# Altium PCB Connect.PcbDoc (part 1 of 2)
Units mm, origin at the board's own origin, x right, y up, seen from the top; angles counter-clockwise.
Board outline 500 x 50 mm, 2 copper layers (Top Layer, Bottom Layer); 349 components, 200 nets, 1152 pads, 307 vias.
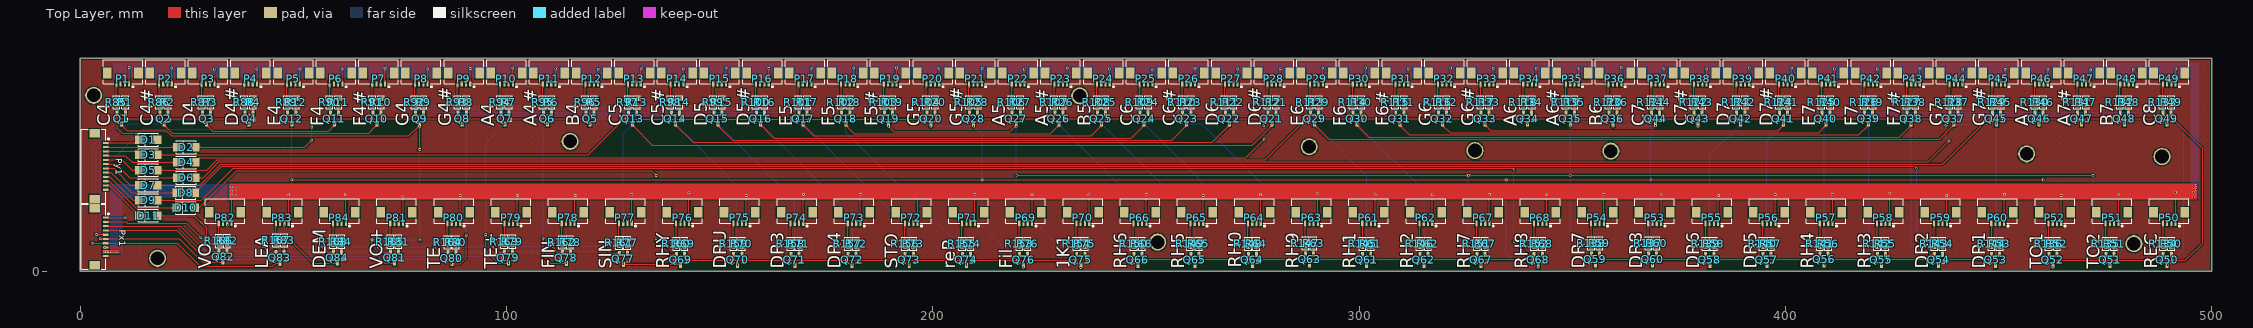
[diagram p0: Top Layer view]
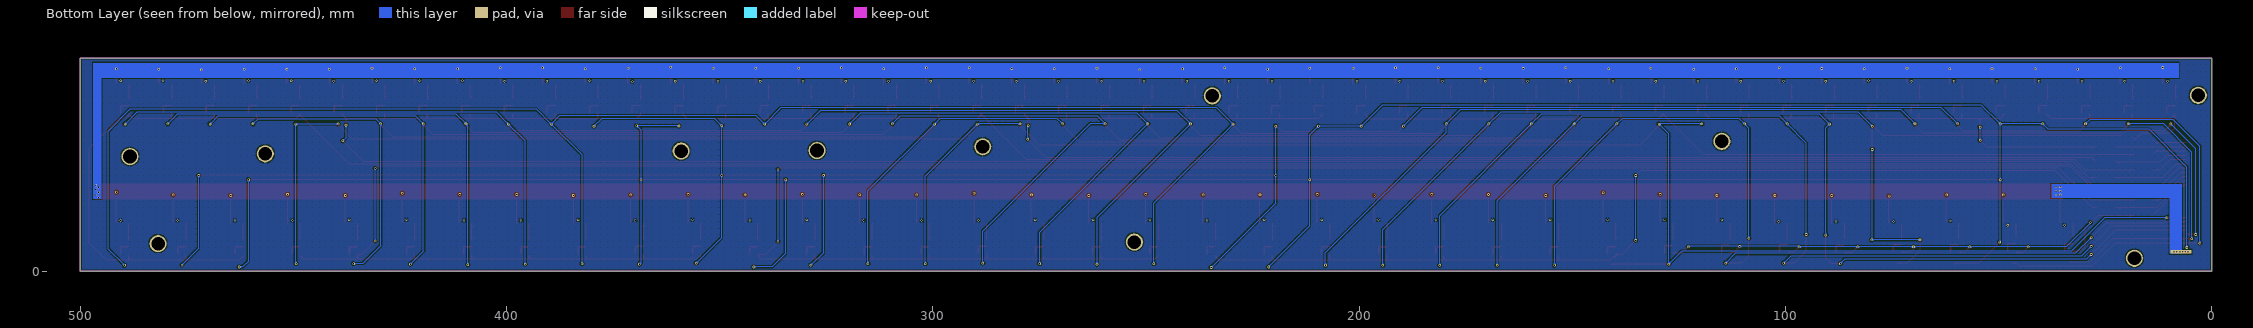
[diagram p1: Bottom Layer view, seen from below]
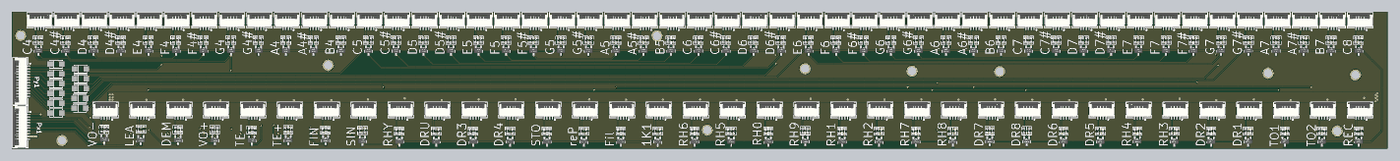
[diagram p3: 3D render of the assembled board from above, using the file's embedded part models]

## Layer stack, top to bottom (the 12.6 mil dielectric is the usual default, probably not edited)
Top Solder: solder mask 0.0102, Solder Resist, Dk 3.5
Top Layer: signal copper 0.0356
Dielectric 1: dielectric 0.32, FR-4, Dk 4.8
Bottom Layer: signal copper 0.0356
Bottom Solder: solder mask 0.0102, Solder Resist, Dk 3.5

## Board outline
0,0 500,0 500,50 0,50

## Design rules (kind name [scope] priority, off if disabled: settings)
Clearance [All] p1: gap=0.254
PolygonConnect [All] p1: connectstyle=Relief reliefconductorwidth=0.254 reliefentries=4 polygonreliefangle="90 Angle" airgapwidth=0.254
RoutingVias [All] p1: holewidth=0.3 width=0.6 viastyle="Through Hole" minholewidth=0.3 minwidth=0.6 maxholewidth=0.711 maxwidth=1.27
SolderMaskExpansion [All] p1: expansion=0.102
Width [All] p1: maxlimit=0.254 minlimit=0.254 preferedwidth=0.254
30 further rules are at their usual default settings.

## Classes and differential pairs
component class Sheet3: D1 D2 D3 D4 D5 D6 D7 D8 D9 D10 D11 Px1 Py1 Q1 Q2 Q3 Q4 Q5 Q6 Q7 Q8 Q9 Q10 Q11 Q12 Q13 Q14 Q15 Q16 Q17 Q18 Q19 Q20 Q21 Q22 Q23 Q24 Q25 Q26 Q27 Q28 Q29 Q30 Q31 Q32 Q33 Q34 Q35 Q36 Q37 Q38 Q39 Q40 Q41 Q42 Q43 Q44 Q45 Q46 Q47 Q48 Q49 Q50 Q51 Q52 Q53 Q54 Q55 Q56 Q57 Q58 Q59 Q60 Q61 Q62 Q63 Q64 Q65 Q66 Q67 Q68 Q69 Q70 Q71 Q72 Q73 Q74 Q75 Q76 Q77 Q79 Q80 Q81 Q82 Q83 Q84 R1 R2 R3 R4 R5 R6 R7 R8 R9 R10 R11 R12 R13 R14 R15 R16 R17 R18 R19 R20 R21 R22 R23 R24 R25 R26 R27 R28 R29 R30 R31 R32 R33 R34 R35 R36 R37 R38 R39 R40 R41 R42 R43 R44 R45 R46 R47 R48 R49 R50 R51 R52 R53 R54 R55 R56 R57 R58 R59 R60 R61 R62 R63 R64 R65 R66 R67 R68 R69 R70 R71 R72 R73 R74 R75 R76 R77 R79 R80 R81 R82 R83 R84
component class CONNECT: P21 P22 P23 P24 P25 P26 P27 P28 P29 P30 P31 P32 P33 P34 P35 P36 P37 P38 P39 P40 P41 P42 P43 P44 P45 P46 P47 P48 P49 P50 P51 P52 P53 P54 P55 P56 P57 P58 P59 P60 P61 P62 P63 P64 P65 P66 P67 P68 P69 P70 P71 P72 P73 P74 P75 P76 P77 P78 P79 P80 P81 P82 P83 P84 R105 R106 R107 R108 R109 R110 R111 R112 R113 R114 R115 R116 R117 R118 R119 R120 R121 R122 R123 R124 R125 R126 R127 R128 R129 R130 R131 R132 R133 R134 R135 R136 R137 R138 R139 R140 R141 R142 R143 R144 R145 R146 R147 R148 R149 R150 R151 R152 R153 R154 R155 R156 R157 R158 R159 R160 R161 R163 R164 R165 R166 R167 R168
component class CONNECT2: P1 P2 P3 P4 P5 P6 P7 P8 P9 P10 P11 P12 P13 P14 P15 P16 P17 P18 P19 P20 R85 R86 R87 R88 R89 R90 R91 R92 R93 R94 R95 R96 R97 R98 R99 R100 R101 R102 R103 R104

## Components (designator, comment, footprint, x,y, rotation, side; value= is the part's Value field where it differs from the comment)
D1 "M7" SMA(DO-214AC)_S1 16.002,30.861 r0 top
D2 "M7" SMA(DO-214AC)_S1 24.892,29.083 r0 top
D3 "M7" SMA(DO-214AC)_S1 16.002,27.305 r0 top
D4 "M7" SMA(DO-214AC)_S1 24.892,25.527 r0 top
D5 "M7" SMA(DO-214AC)_S1 16.002,23.749 r0 top
D6 "M7" SMA(DO-214AC)_S1 24.892,21.971 r0 top
D7 "M7" SMA(DO-214AC)_S1 16.002,20.193 r0 top
D8 "M7" SMA(DO-214AC)_S1 24.765,18.415 r0 top
D9 "M7" SMA(DO-214AC)_S1 16.002,16.637 r0 top
D10 "M7" SMA(DO-214AC)_S1 24.765,14.859 r0 top
D11 "M7" SMA(DO-214AC)_S1 16.002,13.081 r0 top
P1 "Header 4" FPC1.0-2H-WS-4P 10,46.5 r180 top
P2 "Header 4" FPC1.0-2H-WS-4P 20,46.5 r180 top
P3 "Header 4" FPC1.0-2H-WS-4P 30,46.5 r180 top
P4 "Header 4" FPC1.0-2H-WS-4P 40,46.5 r180 top
P5 "Header 4" FPC1.0-2H-WS-4P 50,46.5 r180 top
P6 "Header 4" FPC1.0-2H-WS-4P 60,46.5 r180 top
P7 "Header 4" FPC1.0-2H-WS-4P 70,46.5 r180 top
P8 "Header 4" FPC1.0-2H-WS-4P 80,46.5 r180 top
P9 "Header 4" FPC1.0-2H-WS-4P 90,46.5 r180 top
P10 "Header 4" FPC1.0-2H-WS-4P 100,46.5 r180 top
P11 "Header 4" FPC1.0-2H-WS-4P 110,46.5 r180 top
P12 "Header 4" FPC1.0-2H-WS-4P 120,46.5 r180 top
P13 "Header 4" FPC1.0-2H-WS-4P 130,46.5 r180 top
P14 "Header 4" FPC1.0-2H-WS-4P 140,46.5 r180 top
P15 "Header 4" FPC1.0-2H-WS-4P 150,46.5 r180 top
P16 "Header 4" FPC1.0-2H-WS-4P 160,46.5 r180 top
P17 "Header 4" FPC1.0-2H-WS-4P 170,46.5 r180 top
P18 "Header 4" FPC1.0-2H-WS-4P 180,46.5 r180 top
P19 "Header 4" FPC1.0-2H-WS-4P 190,46.5 r180 top
P20 "Header 4" FPC1.0-2H-WS-4P 200,46.5 r180 top
P21 "Header 4" FPC1.0-2H-WS-4P 210,46.5 r180 top
P22 "Header 4" FPC1.0-2H-WS-4P 220,46.5 r180 top
P23 "Header 4" FPC1.0-2H-WS-4P 230,46.5 r180 top
P24 "Header 4" FPC1.0-2H-WS-4P 240,46.5 r180 top
P25 "Header 4" FPC1.0-2H-WS-4P 250,46.5 r180 top
P26 "Header 4" FPC1.0-2H-WS-4P 260,46.5 r180 top
P27 "Header 4" FPC1.0-2H-WS-4P 270,46.5 r180 top
P28 "Header 4" FPC1.0-2H-WS-4P 280,46.5 r180 top
P29 "Header 4" FPC1.0-2H-WS-4P 290,46.5 r180 top
P30 "Header 4" FPC1.0-2H-WS-4P 300,46.5 r180 top
P31 "Header 4" FPC1.0-2H-WS-4P 310,46.5 r180 top
P32 "Header 4" FPC1.0-2H-WS-4P 320,46.5 r180 top
P33 "Header 4" FPC1.0-2H-WS-4P 330,46.5 r180 top
P34 "Header 4" FPC1.0-2H-WS-4P 340,46.5 r180 top
P35 "Header 4" FPC1.0-2H-WS-4P 350,46.5 r180 top
P36 "Header 4" FPC1.0-2H-WS-4P 360,46.5 r180 top
P37 "Header 4" FPC1.0-2H-WS-4P 370,46.5 r180 top
P38 "Header 4" FPC1.0-2H-WS-4P 380,46.5 r180 top
P39 "Header 4" FPC1.0-2H-WS-4P 390,46.5 r180 top
P40 "Header 4" FPC1.0-2H-WS-4P 400,46.5 r180 top
P41 "Header 4" FPC1.0-2H-WS-4P 410,46.5 r180 top
P42 "Header 4" FPC1.0-2H-WS-4P 420,46.5 r180 top
P43 "Header 4" FPC1.0-2H-WS-4P 430,46.5 r180 top
P44 "Header 4" FPC1.0-2H-WS-4P 440,46.5 r180 top
P45 "Header 4" FPC1.0-2H-WS-4P 450,46.5 r180 top
P46 "Header 4" FPC1.0-2H-WS-4P 460,46.5 r180 top
P47 "Header 4" FPC1.0-2H-WS-4P 470,46.5 r180 top
P48 "Header 4" FPC1.0-2H-WS-4P 480,46.5 r180 top
P49 "Header 4" FPC1.0-2H-WS-4P 490,46.5 r180 top
P50 "Header 4" FPC1.0-2H-WS-4P 490,13.843 r180 top
P51 "Header 4" FPC1.0-2H-WS-4P 476.588,13.843 r180 top
P52 "Header 4" FPC1.0-2H-WS-4P 463.177,13.843 r180 top
P53 "Header 4" FPC1.0-2H-WS-4P 369.295,13.843 r180 top
P54 "Header 4" FPC1.0-2H-WS-4P 355.883,13.843 r180 top
P55 "Header 4" FPC1.0-2H-WS-4P 382.706,13.843 r180 top
P56 "Header 4" FPC1.0-2H-WS-4P 396.118,13.843 r180 top
P57 "Header 4" FPC1.0-2H-WS-4P 409.53,13.843 r180 top
P58 "Header 4" FPC1.0-2H-WS-4P 422.942,13.843 r180 top
P59 "Header 4" FPC1.0-2H-WS-4P 436.353,13.843 r180 top
P60 "Header 4" FPC1.0-2H-WS-4P 449.765,13.843 r180 top
P61 "Header 4" FPC1.0-2H-WS-4P 302.236,13.843 r180 top
P62 "Header 4" FPC1.0-2H-WS-4P 315.648,13.843 r180 top
P63 "Header 4" FPC1.0-2H-WS-4P 288.825,13.843 r180 top
P64 "Header 4" FPC1.0-2H-WS-4P 275.413,13.843 r180 top
P65 "Header 4" FPC1.0-2H-WS-4P 261.92,13.843 r180 top
P66 "Header 4" FPC1.0-2H-WS-4P 248.59,13.843 r180 top
P67 "Header 4" FPC1.0-2H-WS-4P 329.06,13.843 r180 top
P68 "Header 4" FPC1.0-2H-WS-4P 342.471,13.843 r180 top
P69 "Header 4" FPC1.0-2H-WS-4P 221.766,13.843 r180 top
P70 "Header 4" FPC1.0-2H-WS-4P 235.178,13.843 r180 top
P71 "Header 4" FPC1.0-2H-WS-4P 208.355,13.843 r180 top
P72 "Header 4" FPC1.0-2H-WS-4P 194.943,13.843 r180 top
P73 "Header 4" FPC1.0-2H-WS-4P 181.531,13.843 r180 top
P74 "Header 4" FPC1.0-2H-WS-4P 168.12,13.843 r180 top
P75 "Header 4" FPC1.0-2H-WS-4P 154.708,13.843 r180 top
P76 "Header 4" FPC1.0-2H-WS-4P 141.296,13.843 r180 top
P77 "Header 4" FPC1.0-2H-WS-4P 127.885,13.843 r180 top
P78 "Header 4" FPC1.0-2H-WS-4P 114.473,13.843 r180 top
P79 "Header 4" FPC1.0-2H-WS-4P 101.061,13.843 r180 top
P80 "Header 4" FPC1.0-2H-WS-4P 87.65,13.843 r180 top
P81 "Header 4" FPC1.0-2H-WS-4P 74.238,13.843 r180 top
P82 "Header 4" FPC1.0-2H-WS-4P 34.003,13.843 r180 top
P83 "Header 4" FPC1.0-2H-WS-4P 47.415,13.843 r180 top
P84 "Header 4" FPC1.0-2H-WS-4P 60.826,13.843 r180 top
Px1 "Header 10" FPC1.0-2H-WS-10P 3.429,8.087 r270 top
Py1 "Header 12" FPC1.0-2H-WS-12P 3.429,24.638 r270 top
Q1 "SS8050 Y1" SOT-23(SOT-23-3) 9.652,35.814 r90 top
Q2 "SS8050 Y1" SOT-23(SOT-23-3) 19.648,35.814 r90 top
Q3 "SS8050 Y1" SOT-23(SOT-23-3) 29.644,35.814 r90 top
Q4 "SS8050 Y1" SOT-23(SOT-23-3) 39.64,35.814 r90 top
Q5 "SS8050 Y1" SOT-23(SOT-23-3) 119.608,35.814 r90 top
Q6 "SS8050 Y1" SOT-23(SOT-23-3) 109.612,35.814 r90 top
Q7 "SS8050 Y1" SOT-23(SOT-23-3) 99.616,35.814 r90 top
Q8 "SS8050 Y1" SOT-23(SOT-23-3) 89.62,35.814 r90 top
Q9 "SS8050 Y1" SOT-23(SOT-23-3) 79.624,35.814 r90 top
Q10 "SS8050 Y1" SOT-23(SOT-23-3) 69.628,35.814 r90 top
Q11 "SS8050 Y1" SOT-23(SOT-23-3) 59.632,35.814 r90 top
Q12 "SS8050 Y1" SOT-23(SOT-23-3) 49.636,35.814 r90 top
Q13 "SS8050 Y1" SOT-23(SOT-23-3) 129.603,35.814 r90 top
Q14 "SS8050 Y1" SOT-23(SOT-23-3) 139.599,35.814 r90 top
Q15 "SS8050 Y1" SOT-23(SOT-23-3) 149.595,35.814 r90 top
Q16 "SS8050 Y1" SOT-23(SOT-23-3) 159.591,35.814 r90 top
Q17 "SS8050 Y1" SOT-23(SOT-23-3) 169.587,35.814 r90 top
Q18 "SS8050 Y1" SOT-23(SOT-23-3) 179.583,35.814 r90 top
Q19 "SS8050 Y1" SOT-23(SOT-23-3) 189.579,35.814 r90 top
Q20 "SS8050 Y1" SOT-23(SOT-23-3) 199.575,35.814 r90 top
Q21 "SS8050 Y1" SOT-23(SOT-23-3) 279.543,35.814 r90 top
Q22 "SS8050 Y1" SOT-23(SOT-23-3) 269.547,35.814 r90 top
Q23 "SS8050 Y1" SOT-23(SOT-23-3) 259.551,35.814 r90 top
Q24 "SS8050 Y1" SOT-23(SOT-23-3) 249.555,35.814 r90 top
Q25 "SS8050 Y1" SOT-23(SOT-23-3) 239.559,35.814 r90 top
Q26 "SS8050 Y1" SOT-23(SOT-23-3) 229.563,35.814 r90 top
Q27 "SS8050 Y1" SOT-23(SOT-23-3) 219.567,35.814 r90 top
Q28 "SS8050 Y1" SOT-23(SOT-23-3) 209.571,35.814 r90 top
Q29 "SS8050 Y1" SOT-23(SOT-23-3) 289.539,35.814 r90 top
Q30 "SS8050 Y1" SOT-23(SOT-23-3) 299.535,35.814 r90 top
Q31 "SS8050 Y1" SOT-23(SOT-23-3) 309.531,35.814 r90 top
Q32 "SS8050 Y1" SOT-23(SOT-23-3) 319.527,35.814 r90 top
Q33 "SS8050 Y1" SOT-23(SOT-23-3) 329.523,35.814 r90 top
Q34 "SS8050 Y1" SOT-23(SOT-23-3) 339.519,35.814 r90 top
Q35 "SS8050 Y1" SOT-23(SOT-23-3) 349.515,35.814 r90 top
Q36 "SS8050 Y1" SOT-23(SOT-23-3) 359.51,35.814 r90 top
Q37 "SS8050 Y1" SOT-23(SOT-23-3) 439.478,35.814 r90 top
Q38 "SS8050 Y1" SOT-23(SOT-23-3) 429.482,35.814 r90 top
Q39 "SS8050 Y1" SOT-23(SOT-23-3) 419.486,35.814 r90 top
Q40 "SS8050 Y1" SOT-23(SOT-23-3) 409.49,35.814 r90 top
Q41 "SS8050 Y1" SOT-23(SOT-23-3) 399.494,35.814 r90 top
Q42 "SS8050 Y1" SOT-23(SOT-23-3) 389.498,35.814 r90 top
Q43 "SS8050 Y1" SOT-23(SOT-23-3) 379.502,35.814 r90 top
Q44 "SS8050 Y1" SOT-23(SOT-23-3) 369.506,35.814 r90 top
Q45 "SS8050 Y1" SOT-23(SOT-23-3) 449.474,35.814 r90 top
Q46 "SS8050 Y1" SOT-23(SOT-23-3) 459.47,35.814 r90 top
Q47 "SS8050 Y1" SOT-23(SOT-23-3) 469.466,35.814 r90 top
Q48 "SS8050 Y1" SOT-23(SOT-23-3) 479.462,35.814 r90 top
Q49 "SS8050 Y1" SOT-23(SOT-23-3) 489.458,35.814 r90 top
Q50 "SS8050 Y1" SOT-23(SOT-23-3) 489.533,2.687 r90 top
Q51 "SS8050 Y1" SOT-23(SOT-23-3) 476.121,2.687 r90 top
Q52 "SS8050 Y1" SOT-23(SOT-23-3) 462.709,2.687 r90 top
Q53 "SS8050 Y1" SOT-23(SOT-23-3) 449.297,2.687 r90 top
Q54 "SS8050 Y1" SOT-23(SOT-23-3) 435.885,2.687 r90 top
Q55 "SS8050 Y1" SOT-23(SOT-23-3) 422.473,2.687 r90 top
Q56 "SS8050 Y1" SOT-23(SOT-23-3) 409.067,2.794 r90 top
Q57 "SS8050 Y1" SOT-23(SOT-23-3) 395.649,2.687 r90 top
Q58 "SS8050 Y1" SOT-23(SOT-23-3) 382.237,2.687 r90 top
Q59 "SS8050 Y1" SOT-23(SOT-23-3) 355.414,2.814 r90 top
Q60 "SS8050 Y1" SOT-23(SOT-23-3) 368.826,2.814 r90 top
Q61 "SS8050 Y1" SOT-23(SOT-23-3) 301.766,2.687 r90 top
Q62 "SS8050 Y1" SOT-23(SOT-23-3) 315.178,2.687 r90 top
Q63 "SS8050 Y1" SOT-23(SOT-23-3) 288.354,2.814 r90 top
Q64 "SS8050 Y1" SOT-23(SOT-23-3) 274.942,2.687 r90 top
Q65 "SS8050 Y1" SOT-23(SOT-23-3) 261.449,2.687 r90 top
Q66 "SS8050 Y1" SOT-23(SOT-23-3) 248.118,2.687 r90 top
Q67 "SS8050 Y1" SOT-23(SOT-23-3) 328.59,2.687 r90 top
Q68 "SS8050 Y1" SOT-23(SOT-23-3) 342.002,2.687 r90 top
Q69 "SS8050 Y1" SOT-23(SOT-23-3) 140.823,2.687 r90 top
Q70 "SS8050 Y1" SOT-23(SOT-23-3) 154.235,2.687 r90 top
Q71 "SS8050 Y1" SOT-23(SOT-23-3) 167.647,2.687 r90 top
Q72 "SS8050 Y1" SOT-23(SOT-23-3) 181.059,2.687 r90 top
Q73 "SS8050 Y1" SOT-23(SOT-23-3) 194.471,2.687 r90 top
Q74 "SS8050 Y1" SOT-23(SOT-23-3) 207.883,2.687 r90 top
Q75 "SS8050 Y1" SOT-23(SOT-23-3) 234.707,2.687 r90 top
Q76 "SS8050 Y1" SOT-23(SOT-23-3) 221.295,2.687 r90 top
Q77 "SS8050 Y1" SOT-23(SOT-23-3) 127.411,2.941 r90 top
Q78 "SS8050 Y1" SOT-23(SOT-23-3) 114.046,3.155 r90 top
Q79 "SS8050 Y1" SOT-23(SOT-23-3) 100.461,3.195 r90 top
Q80 "SS8050 Y1" SOT-23(SOT-23-3) 87.176,3.068 r90 top
Q81 "SS8050 Y1" SOT-23(SOT-23-3) 73.764,3.195 r90 top
Q82 "SS8050 Y1" SOT-23(SOT-23-3) 33.528,3.429 r90 top
Q83 "SS8050 Y1" SOT-23(SOT-23-3) 46.863,3.155 r90 top
Q84 "SS8050 Y1" SOT-23(SOT-23-3) 60.352,3.195 r90 top
R1 "10KΩ (1002) ±1%" 0603_R 10.561,39.624 r270 top
R2 "10KΩ (1002) ±1%" 0603_R 20.559,39.624 r270 top
R3 "10KΩ (1002) ±1%" 0603_R 30.557,39.624 r270 top
R4 "10KΩ (1002) ±1%" 0603_R 40.556,39.624 r270 top
R5 "10KΩ (1002) ±1%" 0603_R 120.541,39.624 r270 top
R6 "10KΩ (1002) ±1%" 0603_R 110.543,39.624 r270 top
R7 "10KΩ (1002) ±1%" 0603_R 100.545,39.624 r270 top
R8 "10KΩ (1002) ±1%" 0603_R 90.547,39.624 r270 top
R9 "10KΩ (1002) ±1%" 0603_R 80.548,39.624 r270 top
R10 "10KΩ (1002) ±1%" 0603_R 70.55,39.624 r270 top
R11 "10KΩ (1002) ±1%" 0603_R 60.552,39.624 r270 top
R12 "10KΩ (1002) ±1%" 0603_R 50.554,39.624 r270 top
R13 "10KΩ (1002) ±1%" 0603_R 130.539,39.624 r270 top
R14 "10KΩ (1002) ±1%" 0603_R 140.537,39.624 r270 top
R15 "10KΩ (1002) ±1%" 0603_R 150.536,39.624 r270 top
R16 "10KΩ (1002) ±1%" 0603_R 160.534,39.624 r270 top
R17 "10KΩ (1002) ±1%" 0603_R 170.532,39.624 r270 top
R18 "10KΩ (1002) ±1%" 0603_R 180.53,39.624 r270 top
R19 "10KΩ (1002) ±1%" 0603_R 190.528,39.624 r270 top
R20 "10KΩ (1002) ±1%" 0603_R 200.527,39.624 r270 top
R21 "10KΩ (1002) ±1%" 0603_R 280.512,39.624 r270 top
R22 "10KΩ (1002) ±1%" 0603_R 270.514,39.624 r270 top
R23 "10KΩ (1002) ±1%" 0603_R 260.516,39.624 r270 top
R24 "10KΩ (1002) ±1%" 0603_R 250.518,39.624 r270 top
R25 "10KΩ (1002) ±1%" 0603_R 240.519,39.624 r270 top
R26 "10KΩ (1002) ±1%" 0603_R 230.521,39.624 r270 top
R27 "10KΩ (1002) ±1%" 0603_R 220.523,39.624 r270 top
R28 "10KΩ (1002) ±1%" 0603_R 210.525,39.624 r270 top
R29 "10KΩ (1002) ±1%" 0603_R 290.51,39.624 r270 top
R30 "10KΩ (1002) ±1%" 0603_R 300.508,39.624 r270 top
R31 "10KΩ (1002) ±1%" 0603_R 310.507,39.624 r270 top
R32 "10KΩ (1002) ±1%" 0603_R 320.505,39.624 r270 top
R33 "10KΩ (1002) ±1%" 0603_R 330.503,39.624 r270 top
R34 "10KΩ (1002) ±1%" 0603_R 340.501,39.624 r270 top
R35 "10KΩ (1002) ±1%" 0603_R 350.499,39.624 r270 top
R36 "10KΩ (1002) ±1%" 0603_R 360.498,39.624 r270 top
R37 "10KΩ (1002) ±1%" 0603_R 440.483,39.624 r270 top
R38 "10KΩ (1002) ±1%" 0603_R 430.485,39.624 r270 top
R39 "10KΩ (1002) ±1%" 0603_R 420.487,39.624 r270 top
R40 "10KΩ (1002) ±1%" 0603_R 410.489,39.624 r270 top
R41 "10KΩ (1002) ±1%" 0603_R 400.49,39.624 r270 top
R42 "10KΩ (1002) ±1%" 0603_R 390.492,39.624 r270 top
R43 "10KΩ (1002) ±1%" 0603_R 380.494,39.624 r270 top
R44 "10KΩ (1002) ±1%" 0603_R 370.496,39.624 r270 top
R45 "10KΩ (1002) ±1%" 0603_R 450.481,39.624 r270 top
R46 "10KΩ (1002) ±1%" 0603_R 460.479,39.624 r270 top
R47 "10KΩ (1002) ±1%" 0603_R 470.478,39.624 r270 top
R48 "10KΩ (1002) ±1%" 0603_R 480.476,39.624 r270 top
R49 "10KΩ (1002) ±1%" 0603_R 490.474,39.624 r270 top
R50 "10KΩ (1002) ±1%" 0603_R 490.474,6.477 r270 top
R51 "10KΩ (1002) ±1%" 0603_R 477.062,6.477 r270 top
R52 "10KΩ (1002) ±1%" 0603_R 463.649,6.477 r270 top
R53 "10KΩ (1002) ±1%" 0603_R 450.237,6.477 r270 top
R54 "10KΩ (1002) ±1%" 0603_R 436.824,6.477 r270 top
R55 "10KΩ (1002) ±1%" 0603_R 423.412,6.477 r270 top
R56 "10KΩ (1002) ±1%" 0603_R 410,6.477 r270 top
R57 "10KΩ (1002) ±1%" 0603_R 396.587,6.477 r270 top
R58 "10KΩ (1002) ±1%" 0603_R 383.175,6.477 r270 top
R59 "10KΩ (1002) ±1%" 0603_R 356.35,6.604 r270 top
R60 "10KΩ (1002) ±1%" 0603_R 369.763,6.604 r270 top
R61 "10KΩ (1002) ±1%" 0603_R 302.701,6.477 r270 top
R62 "10KΩ (1002) ±1%" 0603_R 316.113,6.477 r270 top
R63 "10KΩ (1002) ±1%" 0603_R 289.288,6.604 r270 top
R64 "10KΩ (1002) ±1%" 0603_R 275.876,6.477 r270 top
R65 "10KΩ (1002) ±1%" 0603_R 262.382,6.477 r270 top
R66 "10KΩ (1002) ±1%" 0603_R 249.051,6.477 r270 top
R67 "10KΩ (1002) ±1%" 0603_R 329.526,6.477 r270 top
R68 "10KΩ (1002) ±1%" 0603_R 342.938,6.477 r270 top
R69 "10KΩ (1002) ±1%" 0603_R 141.752,6.477 r270 top
R70 "10KΩ (1002) ±1%" 0603_R 155.165,6.477 r270 top
R71 "10KΩ (1002) ±1%" 0603_R 168.577,6.477 r270 top
R72 "10KΩ (1002) ±1%" 0603_R 181.99,6.477 r270 top
R73 "10KΩ (1002) ±1%" 0603_R 195.402,6.477 r270 top
R74 "10KΩ (1002) ±1%" 0603_R 208.814,6.477 r270 top
R75 "10KΩ (1002) ±1%" 0603_R 235.639,6.477 r270 top
R76 "10KΩ (1002) ±1%" 0603_R 222.227,6.477 r270 top
R77 "10KΩ (1002) ±1%" 0603_R 128.34,6.731 r270 top
R78 "10KΩ (1002) ±1%" 0603_R 114.928,6.858 r270 top
R79 "10KΩ (1002) ±1%" 0603_R 101.388,6.985 r270 top
R80 "10KΩ (1002) ±1%" 0603_R 88.103,6.858 r270 top
R81 "10KΩ (1002) ±1%" 0603_R 74.691,6.985 r270 top
R82 "10KΩ (1002) ±1%" 0603_R 34.454,7.112 r270 top
R83 "10KΩ (1002) ±1%" 0603_R 47.866,7.239 r270 top
R84 "10KΩ (1002) ±1%" 0603_R 61.278,6.985 r270 top
R85 "1KΩ (1001) ±1%" 0603_R 8.509,39.624 r90 top
R86 "1KΩ (1001) ±1%" 0603_R 18.508,39.624 r90 top
R87 "1KΩ (1001) ±1%" 0603_R 28.506,39.624 r90 top
R88 "1KΩ (1001) ±1%" 0603_R 38.505,39.624 r90 top
R89 "1KΩ (1001) ±1%" 0603_R 48.503,39.624 r90 top
R90 "1KΩ (1001) ±1%" 0603_R 58.502,39.624 r90 top
R91 "1KΩ (1001) ±1%" 0603_R 68.501,39.624 r90 top
R92 "1KΩ (1001) ±1%" 0603_R 78.499,39.624 r90 top
R93 "1KΩ (1001) ±1%" 0603_R 88.498,39.624 r90 top
R94 "1KΩ (1001) ±1%" 0603_R 98.496,39.624 r90 top
R95 "1KΩ (1001) ±1%" 0603_R 108.495,39.624 r90 top
R96 "1KΩ (1001) ±1%" 0603_R 118.494,39.624 r90 top
R97 "1KΩ (1001) ±1%" 0603_R 128.492,39.624 r90 top
R98 "1KΩ (1001) ±1%" 0603_R 138.491,39.624 r90 top
R99 "1KΩ (1001) ±1%" 0603_R 148.489,39.624 r90 top
R100 "1KΩ (1001) ±1%" 0603_R 158.488,39.624 r90 top
R101 "1KΩ (1001) ±1%" 0603_R 168.487,39.624 r90 top
R102 "1KΩ (1001) ±1%" 0603_R 178.485,39.624 r90 top
R103 "1KΩ (1001) ±1%" 0603_R 188.484,39.624 r90 top
R104 "1KΩ (1001) ±1%" 0603_R 198.482,39.624 r90 top
R105 "1KΩ (1001) ±1%" 0603_R 208.481,39.624 r90 top
R106 "1KΩ (1001) ±1%" 0603_R 218.48,39.624 r90 top
R107 "1KΩ (1001) ±1%" 0603_R 228.478,39.624 r90 top
R108 "1KΩ (1001) ±1%" 0603_R 238.477,39.624 r90 top
R109 "1KΩ (1001) ±1%" 0603_R 248.475,39.624 r90 top
R110 "1KΩ (1001) ±1%" 0603_R 258.474,39.624 r90 top
R111 "1KΩ (1001) ±1%" 0603_R 268.473,39.624 r90 top
R112 "1KΩ (1001) ±1%" 0603_R 278.471,39.624 r90 top
R113 "1KΩ (1001) ±1%" 0603_R 288.47,39.624 r90 top
R114 "1KΩ (1001) ±1%" 0603_R 298.468,39.624 r90 top
R115 "1KΩ (1001) ±1%" 0603_R 308.467,39.624 r90 top
R116 "1KΩ (1001) ±1%" 0603_R 318.466,39.624 r90 top
R117 "1KΩ (1001) ±1%" 0603_R 328.464,39.624 r90 top
R118 "1KΩ (1001) ±1%" 0603_R 338.463,39.624 r90 top
R119 "1KΩ (1001) ±1%" 0603_R 348.462,39.624 r90 top
R120 "1KΩ (1001) ±1%" 0603_R 358.46,39.624 r90 top
R121 "1KΩ (1001) ±1%" 0603_R 368.459,39.624 r90 top
R122 "1KΩ (1001) ±1%" 0603_R 378.457,39.624 r90 top
R123 "1KΩ (1001) ±1%" 0603_R 388.456,39.624 r90 top
R124 "1KΩ (1001) ±1%" 0603_R 398.455,39.624 r90 top
R125 "1KΩ (1001) ±1%" 0603_R 408.453,39.624 r90 top
R126 "1KΩ (1001) ±1%" 0603_R 418.452,39.624 r90 top
R127 "1KΩ (1001) ±1%" 0603_R 428.45,39.624 r90 top
R128 "1KΩ (1001) ±1%" 0603_R 438.449,39.624 r90 top
R129 "1KΩ (1001) ±1%" 0603_R 448.448,39.624 r90 top
R130 "1KΩ (1001) ±1%" 0603_R 458.446,39.624 r90 top
R131 "1KΩ (1001) ±1%" 0603_R 468.445,39.624 r90 top
R132 "1KΩ (1001) ±1%" 0603_R 478.443,39.624 r90 top
R133 "1KΩ (1001) ±1%" 0603_R 488.442,39.624 r90 top
R134 "1KΩ (1001) ±1%" 0603_R 488.569,6.477 r90 top
R135 "1KΩ (1001) ±1%" 0603_R 475.156,6.477 r90 top
R136 "1KΩ (1001) ±1%" 0603_R 461.744,6.477 r90 top
R137 "1KΩ (1001) ±1%" 0603_R 367.858,6.604 r90 top
R138 "1KΩ (1001) ±1%" 0603_R 354.445,6.604 r90 top
R139 "1KΩ (1001) ±1%" 0603_R 381.27,6.477 r90 top
R140 "1KΩ (1001) ±1%" 0603_R 394.682,6.477 r90 top
R141 "1KΩ (1001) ±1%" 0603_R 408.095,6.477 r90 top
R142 "1KΩ (1001) ±1%" 0603_R 421.507,6.477 r90 top
R143 "1KΩ (1001) ±1%" 0603_R 434.919,6.477 r90 top
R144 "1KΩ (1001) ±1%" 0603_R 448.332,6.477 r90 top
R145 "1KΩ (1001) ±1%" 0603_R 300.796,6.477 r90 top
R146 "1KΩ (1001) ±1%" 0603_R 314.208,6.477 r90 top
R147 "1KΩ (1001) ±1%" 0603_R 287.383,6.604 r90 top
R148 "1KΩ (1001) ±1%" 0603_R 273.971,6.477 r90 top
R149 "1KΩ (1001) ±1%" 0603_R 260.35,6.477 r90 top
R150 "1KΩ (1001) ±1%" 0603_R 247.146,6.477 r90 top
R151 "1KΩ (1001) ±1%" 0603_R 327.62,6.477 r90 top
R152 "1KΩ (1001) ±1%" 0603_R 341.033,6.477 r90 top
R153 "1KΩ (1001) ±1%" 0603_R 220.322,6.477 r90 top
R154 "1KΩ (1001) ±1%" 0603_R 233.734,6.477 r90 top
R155 "1KΩ (1001) ±1%" 0603_R 206.909,6.477 r90 top
R156 "1KΩ (1001) ±1%" 0603_R 193.497,6.477 r90 top
R157 "1KΩ (1001) ±1%" 0603_R 180.084,6.477 r90 top
R158 "1KΩ (1001) ±1%" 0603_R 166.672,6.477 r90 top
R159 "1KΩ (1001) ±1%" 0603_R 153.26,6.477 r90 top
R160 "1KΩ (1001) ±1%" 0603_R 139.847,6.477 r90 top
R161 "1KΩ (1001) ±1%" 0603_R 126.435,6.731 r90 top
R162 "1KΩ (1001) ±1%" 0603_R 113.023,6.858 r90 top
R163 "1KΩ (1001) ±1%" 0603_R 99.483,6.985 r90 top
R164 "1KΩ (1001) ±1%" 0603_R 86.198,6.858 r90 top
R165 "1KΩ (1001) ±1%" 0603_R 72.786,6.985 r90 top
R166 "1KΩ (1001) ±1%" 0603_R 32.549,7.112 r90 top
R167 "1KΩ (1001) ±1%" 0603_R 45.961,7.239 r90 top
R168 "1KΩ (1001) ±1%" 0603_R 59.373,6.985 r90 top

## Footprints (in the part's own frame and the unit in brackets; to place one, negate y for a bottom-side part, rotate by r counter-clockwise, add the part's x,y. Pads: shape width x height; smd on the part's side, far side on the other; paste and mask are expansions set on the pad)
0603_R [mm]
  rect 0.93x0.98 smd: 1(-0.77,0) 2(0.77,0)
  silkscreen extent -1.54,-0.79 1.54,0.79, body extent -0.85,-0.4 0.85,0.4, height 0.56
FPC1.0-2H-WS-4P [mm] "翻盖FPC，脚距1mm，不含脚（长8.9mm，宽5.2mm，高1.96mm）"
  rect 2x2.5 smd: 0(-3.69,0) 0(3.69,0)
  rect 0.5x1.25 smd: 1(-1.5,2.575) 2(-0.5,2.575) 3(0.5,2.575) 4(1.5,2.575)
  silkscreen extent -4.64,-3.17 4.64,3.31, body extent -4.45,-3.15 4.45,2.85, height 2
FPC1.0-2H-WS-10P [mm] "翻盖FPC，脚距1mm，不含脚（长14.9mm，宽5.2mm，高1.96mm）"
  rect 2x2.5 smd: 0(-6.69,0) 0(6.69,0)
  rect 0.5x1.25 smd: 1(-4.5,2.575) 2(-3.5,2.575) 3(-2.5,2.575) 4(-1.5,2.575) 5(-0.5,2.575) 6(0.5,2.575) 7(1.5,2.575) 8(2.5,2.575) 9(3.5,2.575) 10(4.5,2.575)
  silkscreen extent -7.64,-3.18 7.64,3.31, body extent -7.45,-3.15 7.45,2.85, height 2
FPC1.0-2H-WS-12P [mm] "翻盖FPC，脚距1mm，不含脚（长16.9mm，宽5.2mm，高1.96mm）"
  rect 2x2.5 smd: 0(-7.69,0) 0(7.69,0)
  rect 0.5x1.25 smd: 1(-5.5,2.575) 2(-4.5,2.575) 3(-3.5,2.575) 4(-2.5,2.575) 5(-1.5,2.575) 6(-0.5,2.575) 7(0.5,2.575) 8(1.5,2.575) 9(2.5,2.575) 10(3.5,2.575) 11(4.5,2.575) 12(5.5,2.575)
  silkscreen extent -8.64,-3.18 8.64,3.31, body extent -8.45,-3.15 8.45,2.85, height 2
SMA(DO-214AC)_S1 [mm]
  rect 2x2 smd: 1(2.1,0) 2(-2.1,0)
  silkscreen extent -2.35,-1.5 2.35,1.5
SOT-23(SOT-23-3) [mm]
  rect 1.25x0.7 smd: 1(1.25,-0.95) 2(1.25,0.95) 3(-1.25,0)
  silkscreen extent -0.65,-1.46 0.9,1.46, body extent -1.5,-1.5 1.5,1.5, height 1.3

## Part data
D1 D2 D3 D4 D5 D6 D7 D8 D9 D10 D11: library part "SMA(DO-214AC) M7", "二极管"
P1 P2 P3 P4 P5 P6 P7 P8 P9 P10 P11 P12 P13 P14 P15 P16 P17 P18 P19 P20 P21 P22 P23 P24 P25 P26 P27 P28 P29 P30 P31 P32 P33 P34 P35 P36 P37 P38 P39 P40 P41 P42 P43 P44 P45 P46 P47 P48 P49 P50 P51 P52 P53 P54 P55 P56 P57 P58 P59 P60 P61 P62 P63 P64 P65 P66 P67 P68 P69 P70 P71 P72 P73 P74 P75 P76 P77 P78 P79 P80 P81 P82 P83 P84: "Header, 4-Pin"
Px1: "Header, 10-Pin"
Py1: "Header, 12-Pin"
Q1 Q2 Q3 Q4 Q5 Q6 Q7 Q8 Q9 Q10 Q11 Q12 Q13 Q14 Q15 Q16 Q17 Q18 Q19 Q20 Q21 Q22 Q23 Q24 Q25 Q26 Q27 Q28 Q29 Q30 Q31 Q32 Q33 Q34 Q35 Q36 Q37 Q38 Q39 Q40 Q41 Q42 Q43 Q44 Q45 Q46 Q47 Q48 Q49 Q50 Q51 Q52 Q53 Q54 Q55 Q56 Q57 Q58 Q59 Q60 Q61 Q62 Q63 Q64 Q65 Q66 Q67 Q68 Q69 Q70 Q71 Q72 Q73 Q74 Q75 Q76 Q77 Q78 Q79 Q80 Q81 Q82 Q83 Q84: library part "SOT-23 SS8050 Y1", "三极管"
R1 R2 R3 R4 R5 R6 R7 R8 R9 R10 R11 R12 R13 R14 R15 R16 R17 R18 R19 R20 R21 R22 R23 R24 R25 R26 R27 R28 R29 R30 R31 R32 R33 R34 R35 R36 R37 R38 R39 R40 R41 R42 R43 R44 R45 R46 R47 R48 R49 R50 R51 R52 R53 R54 R55 R56 R57 R58 R59 R60 R61 R62 R63 R64 R65 R66 R67 R68 R69 R70 R71 R72 R73 R74 R75 R76 R77 R78 R79 R80 R81 R82 R83 R84: library part "0603 10KΩ (1002) 1%", "贴片电阻"
R85 R86 R87 R88 R89 R90 R91 R92 R93 R94 R95 R96 R97 R98 R99 R100 R101 R102 R103 R104 R105 R106 R107 R108 R109 R110 R111 R112 R113 R114 R115 R116 R117 R118 R119 R120 R121 R122 R123 R124 R125 R126 R127 R128 R129 R130 R131 R132 R133 R134 R135 R136 R137 R138 R139 R140 R141 R142 R143 R144 R145 R146 R147 R148 R149 R150 R151 R152 R153 R154 R155 R156 R157 R158 R159 R160 R161 R162 R163 R164 R165 R166 R167 R168: library part "0603 1KΩ (1001) 1%", "贴片电阻"

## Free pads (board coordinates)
  round 4 hole 3.2: 0(3.175,41.275) 3(18.161,3.048) 4(114.935,30.48) 5(288.29,29.21) 6(359.029,28.194) 7(456.565,27.559) 8(488.315,26.924) 9(327.152,28.321) 10(481.711,6.477) 11(252.73,6.858) 12(234.442,41.148)
  rect 5x0.8 smd far side: 2(7.239,4.572)

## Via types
v1: diameter 0.6, hole 0.3, Top Layer to Bottom Layer, 196 vias
v2: diameter 0.5, hole 0.3, Top Layer to Bottom Layer, 111 vias

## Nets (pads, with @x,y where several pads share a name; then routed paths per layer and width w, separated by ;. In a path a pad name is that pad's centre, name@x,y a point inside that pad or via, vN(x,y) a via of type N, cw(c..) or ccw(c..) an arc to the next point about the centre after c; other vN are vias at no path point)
1K1N: Q75.1 R75.2 R154.1 | length 3.7
  Top Layer w0.254: R154.1@233.734,5.707 R75.2@235.639,5.707 235.657,5.707 Q75.1@235.657,3.937
A4: Q7.1 R7.2 R94.1 | length 3.8
  Top Layer w0.254: R94.1@98.496,38.854 R7.2@100.545,38.854 100.545,37.085 Q7.1@100.566,37.064
A4#: Q6.1 R6.2 R95.1 | length 3.8
  Top Layer w0.254: R95.1@108.495,38.854 R6.2@110.543,38.854 110.543,37.083 Q6.1@110.562,37.064
A5: Q27.1 R27.2 R106.1 | length 3.8
  Top Layer w0.254: R106.1@218.48,38.854 R27.2@220.523,38.854 220.523,37.07 Q27.1@220.517,37.064
A5#: Q26.1 R26.2 R107.1 | length 3.8
  Top Layer w0.254: R107.1@228.478,38.854 R26.2@230.521,38.854 230.521,37.072 Q26.1@230.513,37.064
A6: Q34.1 R34.2 R118.1 | length 3.8
  Top Layer w0.254: R118.1@338.463,38.854 R34.2@340.501,38.854 340.501,37.097 Q34.1@340.469,37.064
A6#: Q35.1 R35.2 R119.1 | length 3.8
  Top Layer w0.254: R119.1@348.462,38.854 R35.2@350.499,38.854 350.499,37.099 Q35.1@350.465,37.064
A7: Q46.1 R46.2 R130.1 | length 3.8
  Top Layer w0.254: R130.1@458.446,38.854 R46.2@460.479,38.854 460.479,37.123 Q46.1@460.42,37.064
A7#: Q47.1 R47.2 R131.1 | length 3.8
  Top Layer w0.254: R131.1@468.445,38.854 R47.2@470.478,38.854 470.478,37.126 Q47.1@470.416,37.064
B4: Q5.1 R5.2 R96.1 | length 3.8
  Top Layer w0.254: R96.1@118.494,38.854 R5.2@120.541,38.854 120.541,37.08 Q5.1@120.558,37.064
B5: Q25.1 R25.2 R108.1 | length 3.8
  Top Layer w0.254: R108.1@238.477,38.854 R25.2@240.519,38.854 240.519,37.074 Q25.1@240.509,37.064
B6: Q36.1 R36.2 R120.1 | length 3.8
  Top Layer w0.254: R120.1@358.46,38.854 R36.2@360.498,38.854 360.498,37.101 Q36.1@360.46,37.064
B7: Q48.1 R48.2 R132.1 | length 3.8
  Top Layer w0.254: R132.1@478.443,38.854 R48.2@480.476,38.854 480.476,37.128 Q48.1@480.412,37.064
C4: Q1.1 R1.2 R85.1 | length 3.9
  Top Layer w0.254: R85.1@8.509,38.854 R1.2@10.561,38.854 10.561,37.105 Q1.1@10.602,37.064
C4#: Q2.1 R2.2 R86.1 | length 3.9
  Top Layer w0.254: R86.1@18.508,38.854 R2.2@20.559,38.854 20.559,37.103 Q2.1@20.598,37.064
C5: Q13.1 R13.2 R97.1 | length 3.8
  Top Layer w0.254: R97.1@128.492,38.854 R13.2@130.539,38.854 130.539,37.078 Q13.1@130.553,37.064
C5#: Q14.1 R14.2 R98.1 | length 3.8
  Top Layer w0.254: R98.1@138.491,38.854 R14.2@140.537,38.854 140.537,37.076 Q14.1@140.549,37.064
C6: Q24.1 R24.2 R109.1 | length 3.8
  Top Layer w0.254: R109.1@248.475,38.854 R24.2@250.518,38.854 250.518,37.077 Q24.1@250.505,37.064
C6#: Q23.1 R23.2 R110.1 | length 3.8
  Top Layer w0.254: R110.1@258.474,38.854 R23.2@260.516,38.854 260.516,37.079 Q23.1@260.501,37.064
C7: Q44.1 R44.2 R121.1 | length 3.8
  Top Layer w0.254: R121.1@368.459,38.854 R44.2@370.496,38.854 370.496,37.103 Q44.1@370.456,37.064
C7#: Q43.1 R43.2 R122.1 | length 3.8
  Top Layer w0.254: R122.1@378.457,38.854 R43.2@380.494,38.854 ; Q43.1@380.452,37.064 380.494,37.106 R43.2@380.494,38.854
C8: Q49.1 R49.2 R133.1 | length 3.8
  Top Layer w0.254: R133.1@488.442,38.854 R49.2@490.474,38.854 490.474,37.13 Q49.1@490.408,37.064
D4: Q3.1 R3.2 R87.1 | length 3.9
  Top Layer w0.254: R87.1@28.506,38.854 R3.2@30.557,38.854 30.557,37.101 Q3.1@30.594,37.064
D4#: Q4.1 R4.2 R88.1 | length 3.9
  Top Layer w0.254: R88.1@38.505,38.854 R4.2@40.556,38.854 40.556,37.098 Q4.1@40.59,37.064
D5: Q15.1 R15.2 R99.1 | length 3.8
  Top Layer w0.254: R99.1@148.489,38.854 R15.2@150.536,38.854 150.536,37.074 Q15.1@150.545,37.064
D5#: Q16.1 R16.2 R100.1 | length 3.8
  Top Layer w0.254: R100.1@158.488,38.854 R16.2@160.534,38.854 160.534,37.072 Q16.1@160.541,37.064
D6: Q22.1 R22.2 R111.1 | length 3.8
  Top Layer w0.254: R111.1@268.473,38.854 R22.2@270.514,38.854 270.514,37.081 Q22.1@270.497,37.064
D6#: Q21.1 R21.2 R112.1 | length 3.8
  Top Layer w0.254: R112.1@278.471,38.854 R21.2@280.512,38.854 280.512,37.083 Q21.1@280.493,37.064
D7: Q42.1 R42.2 R123.1 | length 3.8
  Top Layer w0.254: R123.1@388.456,38.854 R42.2@390.492,38.854 390.492,37.108 Q42.1@390.448,37.064
D7#: Q41.1 R41.2 R124.1 | length 3.8
  Top Layer w0.254: R124.1@398.455,38.854 R41.2@400.49,38.854 400.49,37.11 Q41.1@400.444,37.064
DEMO: Q84.1 R84.2 R168.1 | length 3.7
  Top Layer w0.254: R168.1@59.373,6.215 60.325,6.215 R84.2@61.278,6.215 61.278,5.461 61.302,5.438 Q84.1@61.302,4.445
DR1: Q53.1 R53.2 R144.1 | length 3.7
  Top Layer w0.254: R144.1@448.332,5.707 R53.2@450.237,5.707 450.237,3.947 Q53.1@450.247,3.937
DR2: Q54.1 R54.2 R143.1 | length 3.7
  Top Layer w0.254: R143.1@434.919,5.707 R54.2@436.824,5.707 436.824,3.948 Q54.1@436.835,3.937
DR3: Q71.1 R71.2 R158.1 | length 3.7
  Top Layer w0.254: R158.1@166.672,5.707 R71.2@168.577,5.707 168.597,5.707 Q71.1@168.597,3.937
DR4: Q72.1 R72.2 R157.1 | length 3.7
  Top Layer w0.254: R157.1@180.084,5.707 R72.2@181.99,5.707 182.009,5.707 Q72.1@182.009,3.937
DR5: Q57.1 R57.2 R140.1 | length 3.7
  Top Layer w0.254: R140.1@394.682,5.707 R57.2@396.587,5.707 396.587,3.949 Q57.1@396.599,3.937
DR6: Q58.1 R58.2 R139.1 | length 3.7
  Top Layer w0.254: R139.1@381.27,5.707 R58.2@383.175,5.707 383.175,3.949 Q58.1@383.187,3.937
DR7: Q59.1 R59.2 R138.1 | length 3.7
  Top Layer w0.254: R138.1@354.445,5.834 R59.2@356.35,5.834 356.35,4.077 Q59.1@356.364,4.064
DR8: Q60.1 R60.2 R137.1 | length 3.7
  Top Layer w0.254: R137.1@367.858,5.834 R60.2@369.763,5.834 369.763,4.077 Q60.1@369.776,4.064
DRUM: Q70.1 R70.2 R159.1 | length 3.7
  Top Layer w0.254: R159.1@153.26,5.707 R70.2@155.165,5.707 155.185,5.707 Q70.1@155.185,3.937
E4: Q12.1 R12.2 R89.1 | length 3.9
  Top Layer w0.254: R89.1@48.503,38.854 R12.2@50.554,38.854 50.554,37.096 Q12.1@50.586,37.064
E5: Q17.1 R17.2 R101.1 | length 3.8
  Top Layer w0.254: R101.1@168.487,38.854 R17.2@170.532,38.854 170.532,37.069 Q17.1@170.537,37.064
E6: Q29.1 R29.2 R113.1 | length 3.8
  Top Layer w0.254: R113.1@288.47,38.854 R29.2@290.51,38.854 290.51,37.085 Q29.1@290.489,37.064
E7: Q40.1 R40.2 R125.1 | length 3.8
  Top Layer w0.254: R125.1@408.453,38.854 R40.2@410.488,38.854 410.488,37.112 Q40.1@410.44,37.064
F4: Q11.1 R11.2 R90.1 | length 3.9
  Top Layer w0.254: R90.1@58.502,38.854 R11.2@60.552,38.854 60.552,37.094 Q11.1@60.582,37.064
F4#: Q10.1 R10.2 R91.1 | length 3.9
  Top Layer w0.254: R91.1@68.501,38.854 R10.2@70.55,38.854 70.55,37.092 Q10.1@70.578,37.064
F5: Q18.1 R18.2 R102.1 | length 3.8
  Top Layer w0.254: R102.1@178.485,38.854 R18.2@180.53,38.854 180.53,37.067 Q18.1@180.533,37.064
F5#: Q19.1 R19.2 R103.1 | length 3.8
  Top Layer w0.254: R103.1@188.484,38.854 R19.2@190.528,38.854 Q19.1@190.528,37.065
F6: Q30.1 R30.2 R114.1 | length 3.8
  Top Layer w0.254: R114.1@298.468,38.854 R30.2@300.508,38.854 300.508,37.088 Q30.1@300.485,37.064
F6#: Q31.1 R31.2 R115.1 | length 3.8
  Top Layer w0.254: R115.1@308.467,38.854 R31.2@310.507,38.854 310.507,37.09 Q31.1@310.481,37.064
F7: Q39.1 R39.2 R126.1 | length 3.8
  Top Layer w0.254: R126.1@418.452,38.854 R39.2@420.487,38.854 420.487,37.114 Q39.1@420.436,37.064
F7#: Q38.1 R38.2 R127.1 | length 3.8
  Top Layer w0.254: R127.1@428.45,38.854 R38.2@430.485,38.854 430.485,37.117 Q38.1@430.432,37.064
FILLIN: Q76.1 R76.2 R153.1 | length 3.7
  Top Layer w0.254: R153.1@220.322,5.707 R76.2@222.227,5.707 222.245,5.707 Q76.1@222.245,3.937
FINGER: Q78.1 R78.2 R162.1 | length 3.7
  Top Layer w0.254: R162.1@113.023,6.088 R78.2@114.928,6.088 114.949,6.088 Q78.1@114.949,4.318
G4: Q9.1 R9.2 R92.1 | length 3.8
  Top Layer w0.254: R92.1@78.499,38.854 R9.2@80.548,38.854 80.548,37.089 Q9.1@80.574,37.064
G4#: Q8.1 R8.2 R93.1 | length 3.8
  Top Layer w0.254: R93.1@88.498,38.854 R8.2@90.547,38.854 90.547,37.087 Q8.1@90.57,37.064
G5: Q20.1 R20.2 R104.1 | length 3.8
  Top Layer w0.254: R104.1@198.482,38.854 R20.2@200.527,38.854 200.527,37.065 Q20.1@200.525,37.064
G5#: Q28.1 R28.2 R105.1 | length 3.8
  Top Layer w0.254: R105.1@208.481,38.854 R28.2@210.525,38.854 ; Q28.1@210.521,37.064 210.525,37.068 R28.2@210.525,38.854
G6: Q32.1 R32.2 R116.1 | length 3.8
  Top Layer w0.254: R116.1@318.466,38.854 R32.2@320.505,38.854 320.505,37.092 Q32.1@320.477,37.064
G6#: Q33.1 R33.2 R117.1 | length 3.8
  Top Layer w0.254: R117.1@328.464,38.854 R33.2@330.503,38.854 330.503,37.094 Q33.1@330.473,37.064
G7: Q37.1 R37.2 R128.1 | length 3.8
  Top Layer w0.254: R128.1@438.449,38.854 R37.2@440.483,38.854 440.428,38.799 Q37.1@440.428,37.064
G7#: Q45.1 R45.2 R129.1 | length 3.8
  Top Layer w0.254: R129.1@448.448,38.854 R45.2@450.481,38.854 450.481,37.121 Q45.1@450.424,37.064
GND: P1.2 P2.2 P3.2 P4.2 P5.2 P6.2 P7.2 P8.2 P9.2 P10.2 P11.2 P12.2 P13.2 P14.2 P15.2 P16.2 P17.2 P18.2 P19.2 P20.2 P21.2 P22.2 P23.2 P24.2 P25.2 P26.2 P27.2 P28.2 P29.2 P30.2 P31.2 P32.2 P33.2 P34.2 P35.2 P36.2 P37.2 P38.2 P39.2 P40.2 P41.2 P42.2 P43.2 P44.2 P45.2 P46.2 P47.2 P48.2 P49.2 P50.2 P51.2 P52.2 P53.2 P54.2 P55.2 P56.2 P57.2 P58.2 P59.2 P60.2 P61.2 P62.2 P63.2 P64.2 P65.2 P66.2 P67.2 P68.2 P69.2 P70.2 P71.2 P72.2 P73.2 P74.2 P75.2 P76.2 P77.2 P78.2 P79.2 P80.2 P81.2 P82.2 P83.2 P84.2 pad.0 pad.3 pad.4 pad.5 pad.6 pad.7 pad.8 pad.9 pad.10 pad.11 pad.12 Px1.10 R1.1 R2.1 R3.1 R4.1 R5.1 R6.1 R7.1 R8.1 R9.1 R10.1 R11.1 R12.1 R13.1 R14.1 R15.1 R16.1 R17.1 R18.1 R19.1 R20.1 R21.1 R22.1 R23.1 R24.1 R25.1 R26.1 R27.1 R28.1 R29.1 R30.1 R31.1 R32.1 R33.1 R34.1 R35.1 R36.1 R37.1 R38.1 R39.1 R40.1 R41.1 R42.1 R43.1 R44.1 R45.1 R46.1 R47.1 R48.1 R49.1 R50.1 R51.1 R52.1 R53.1 R54.1 R55.1 R56.1 R57.1 R58.1 R59.1 R60.1 R61.1 R62.1 R63.1 R64.1 R65.1 R66.1 R67.1 R68.1 R69.1 R70.1 R71.1 R72.1 R73.1 R74.1 R75.1 R76.1 R77.1 R78.1 R79.1 R80.1 R81.1 R82.1 R83.1 R84.1
  other v2: 34.544,10.795 47.879,10.795 74.676,11.684 88.138,11.684 101.6,11.684 61.341,11.811 235.712,11.938 289.306,11.938 302.641,11.938 316.23,11.938 342.9,11.938 369.824,11.938 396.621,11.938 409.956,11.938 450.215,11.938 463.677,11.938 477.139,11.938 490.474,11.938 114.935,12.065 128.397,12.065 141.732,12.065 155.194,12.065 168.656,12.065 181.991,12.065 195.453,12.065 208.788,12.065 222.25,12.065 249.047,12.065 262.382,12.065 275.971,12.065 329.565,12.065 356.362,12.065 383.159,12.065 423.418,12.065 436.88,12.065 370.459,44.45 10.414,44.577 20.447,44.577 30.48,44.577 40.513,44.577 50.419,44.577 60.452,44.577 70.485,44.577 90.551,44.577 100.457,44.577 110.49,44.577 120.523,44.577 130.429,44.577 140.462,44.577 150.495,44.577 160.528,44.577 170.434,44.577 180.467,44.577 190.5,44.577 200.533,44.577 220.472,44.577 230.505,44.577 240.411,44.577 250.444,44.577 260.477,44.577 270.51,44.577 280.416,44.577 290.449,44.577 300.482,44.577 310.388,44.577 320.421,44.577 330.454,44.577 340.487,44.577 350.393,44.577 360.426,44.577 390.525,44.577 400.431,44.577 440.563,44.577 470.535,44.577 80.518,44.704 380.492,44.704 410.337,44.704 420.37,44.704 430.53,44.704 450.469,44.704 460.502,44.704 480.568,44.704 490.474,44.704
LEARN: Q83.1 R83.2 R167.1 | length 3.7
  Top Layer w0.254: R167.1@45.961,6.469 46.914,6.469 R83.2@47.866,6.469 47.866,5.715 47.89,5.691 Q83.1@47.89,4.679
NetD1_1: D1.1 Q1.2 Q2.2 Q3.2 Q4.2 | length 48.4
  Top Layer w0.254: Q1.2@8.702,37.064 Q1.2@8.702,36.764 ; D1.1@18.669,31.428 D1.1@18.102,30.861 16.578,32.385 9.906,32.385 8.702,33.589 Q1.2@8.702,36.764 ; Q2.2@18.698,37.064 18.698,35.843 18.669,35.814 ; Q3.2@28.694,37.064 28.694,35.822 28.702,35.814 ; Q4.2@38.69,37.064 38.69,36.785 37.719,35.814 28.702,35.814 ; Q1.2@8.702,36.764 9.652,35.814 18.669,35.814 ; 18.669,35.814 28.702,35.814
NetD2_1: D2.1 Q5.2 Q6.2 Q7.2 Q8.2 Q9.2 Q10.2 Q11.2 Q12.2 | length 112.1
  Top Layer w0.254: D2.1@26.992,29.083 52.705,29.083 v1(54.356,30.734) ; Q12.2@48.686,37.064 48.686,36.785 49.657,35.814 54.356,35.814 ; v1(54.356,33.782) 54.356,35.814 ; Q11.2@58.682,37.064 58.682,35.822 58.674,35.814 ; Q10.2@68.678,37.064 68.678,35.843 68.707,35.814 ; Q9.2@78.674,37.064 78.674,35.88 78.74,35.814 ; Q8.2@88.67,37.064 88.67,35.838 88.646,35.814 ; Q7.2@98.666,37.064 98.666,35.827 98.679,35.814 ; Q6.2@108.662,37.064 108.662,35.864 108.712,35.814 ; Q5.2@118.658,37.064 118.658,36.743 117.729,35.814 108.712,35.814 ; 54.356,35.814 58.674,35.814 ; 58.674,35.814 68.707,35.814 ; 68.707,35.814 78.74,35.814 ; 78.74,35.814 88.646,35.814 ; 88.646,35.814 98.679,35.814 ; 98.679,35.814 108.712,35.814
  Bottom Layer w0.254: v1(54.356,30.734) v1(54.356,33.782)
NetD3_1: D3.1 Q13.2 Q14.2 Q15.2 Q16.2 Q17.2 Q18.2 Q19.2 Q20.2 | length 194.3
  Top Layer w0.254: D3.1@18.102,27.305 119.131,27.305 Q13.2@128.653,36.828 ; Q13.2@128.653,37.064 Q13.2@128.653,36.828 ; Q14.2@138.649,37.064 138.649,35.722 138.684,35.687 ; Q15.2@148.645,37.064 148.645,35.742 148.59,35.687 ; Q16.2@158.641,37.064 158.641,35.705 158.623,35.687 ; Q17.2@168.637,37.064 168.637,35.706 168.656,35.687 ; Q18.2@178.633,37.064 178.633,35.758 178.562,35.687 ; Q19.2@188.629,37.064 188.629,35.78 188.722,35.687 ; Q20.2@198.625,37.064 198.625,36.827 197.485,35.687 188.722,35.687 ; Q13.2@128.653,36.828 129.794,35.687 138.684,35.687 ; 138.684,35.687 148.59,35.687 ; 148.59,35.687 158.623,35.687 ; 158.623,35.687 168.656,35.687 ; 168.656,35.687 178.562,35.687 ; 178.562,35.687 188.722,35.687
NetD4_1: D4.1 Q21.2 Q22.2 Q23.2 Q24.2 Q25.2 Q26.2 Q27.2 Q28.2 | length 336.8
  Top Layer w0.254: D4.1@26.992,25.527 28.135,26.67 273.431,26.67 v1(277.749,30.988) ; Q28.2@208.621,37.064 208.621,36.743 209.55,35.814 218.567,35.814 ; Q27.2@218.617,37.064 218.617,35.864 218.567,35.814 ; Q26.2@228.613,37.064 228.613,35.827 228.6,35.814 ; Q25.2@238.609,37.064 238.609,35.838 238.633,35.814 ; Q24.2@248.605,37.064 248.605,35.875 248.666,35.814 ; Q23.2@258.601,37.064 258.601,35.843 258.572,35.814 ; Q22.2@268.597,37.064 268.597,35.822 268.605,35.814 ; v1(277.622,34.163) 277.622,35.814 ; Q21.2@278.593,37.064 278.593,36.785 277.622,35.814 ; 218.567,35.814 228.6,35.814 ; 228.6,35.814 238.633,35.814 ; 238.633,35.814 248.666,35.814 ; 248.666,35.814 258.572,35.814 ; 258.572,35.814 268.605,35.814 ; 268.605,35.814 277.622,35.814
  Bottom Layer w0.254: v1(277.622,34.163) 277.749,34.036 v1(277.749,30.988)
NetD5_1: D5.1 Q29.2 Q30.2 Q31.2 Q32.2 Q33.2 Q34.2 Q35.2 Q36.2 | length 354.8
  Top Layer w0.254: D5.1@18.102,23.749 29.718,23.749 32.131,26.162 277.966,26.162 Q29.2@288.589,36.785 ; Q29.2@288.589,37.064 Q29.2@288.589,36.785 ; Q30.2@298.585,37.064 298.585,35.822 298.577,35.814 ; Q31.2@308.581,37.064 308.581,35.843 308.61,35.814 ; Q32.2@318.577,37.064 318.577,35.875 318.516,35.814 ; Q33.2@328.573,37.064 328.573,35.838 328.549,35.814 ; Q34.2@338.569,37.064 338.569,35.814 ; Q35.2@348.565,37.064 348.565,35.891 348.488,35.814 ; Q36.2@358.56,37.064 358.56,36.742 357.632,35.814 348.488,35.814 ; Q29.2@288.589,36.785 289.56,35.814 298.577,35.814 ; 298.577,35.814 308.61,35.814 ; 308.61,35.814 318.516,35.814 ; 318.516,35.814 328.549,35.814 ; 328.549,35.814 338.569,35.814 ; 338.569,35.814 348.488,35.814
